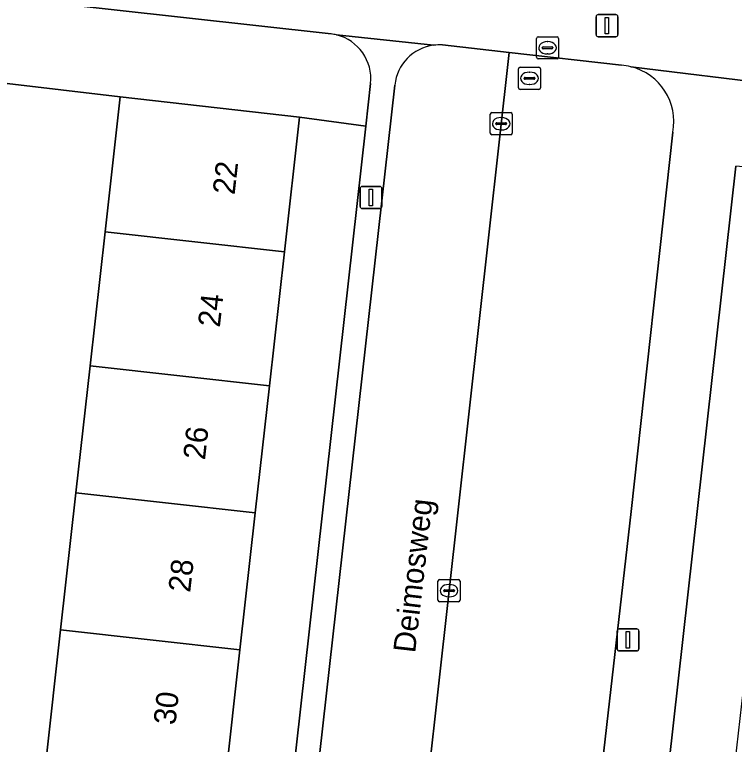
# Model space of a CAD drawing. Extents: x 161928 to 163071, y 386474 to 387428.
# Drawn here: x 162199.57 to 162232.12, y 386884.42 to 386917.4 of the extents above; entities that cross this region are included whole.
import ezdxf

# ---------------------------------------------------------------- set-up
doc = ezdxf.new("R2010")
doc.units = 0
for name, color, linetype in [('IMGEO_Brandkraan', 7, 'Continuous'), ('IMGEO_Erf', 7, 'Continuous'), ('IMGEO_Groenvoorziening', 7, 'Continuous'), ('IMGEO_Kolk', 7, 'Continuous'), ('IMGEO_Lichtmast', 7, 'Continuous'), ('IMGEO_Openbare_ruimte_label', 7, 'Continuous'), ('IMGEO_Pand', 7, 'Continuous'), ('IMGEO_Pand_nummerreeks', 7, 'Continuous'), ('IMGEO_Parkeervlak_open', 7, 'Continuous'), ('IMGEO_Rijbaan_lokaal_open', 7, 'Continuous'), ('IMGEO_Rioolput', 7, 'Continuous'), ('IMGEO_Voetpad_open', 7, 'Continuous')]:
    doc.layers.add(name, color=color, linetype=linetype)

msp = doc.modelspace()

# ---------------------------------------------------------------- linework, layer by layer
at = {"layer": 'IMGEO_Brandkraan'}
for p, q in [((162223.173, 386915.472), (162223.173, 386916.324)), ((162223.248, 386916.398), (162224.1, 386916.398)), ((162223.661, 386916.178), (162223.686, 386916.178)), ((162224.174, 386916.324), (162224.174, 386915.472)), ((162223.432, 386915.892), (162223.432, 386915.904)), ((162223.87, 386915.855), (162223.472, 386915.855)), ((162223.475, 386915.941), (162223.873, 386915.941)), ((162223.916, 386915.904), (162223.916, 386915.892)), ((162223.684, 386915.618), (162223.659, 386915.618)), ((162224.1, 386915.398), (162223.248, 386915.398))]:
    msp.add_line(p, q, dxfattribs=at)
for points in [[(162223.173, 386915.472), (162223.173, 386916.324)], [(162223.248, 386916.398), (162224.1, 386916.398)], [(162224.174, 386916.324), (162224.174, 386915.472)], [(162224.1, 386915.398), (162223.248, 386915.398)]]:
    msp.add_lwpolyline(points, dxfattribs=at)
for centre, radius, start, end in [((162223.25, 386916.322), 0.0765, 91.552, 178.448), ((162223.25, 386916.322), 0.0765, 91.552, 178.448), ((162224.098, 386916.322), 0.0765, 1.552, 88.448), ((162224.098, 386916.322), 0.0765, 1.552, 88.448), ((162223.472, 386915.901), 0.0403, 85.8775, 175.7526), ((162223.469, 386915.891), 0.0366, 178.938, 274.7102), ((162223.873, 386915.898), 0.043, 264.8664, 352.4533), ((162223.877, 386915.903), 0.0386, 1.7309, 96.639), ((162223.25, 386915.474), 0.0765, 181.552, 268.448), ((162223.25, 386915.474), 0.0765, 181.552, 268.448), ((162224.098, 386915.474), 0.0765, 271.552, 358.448), ((162224.098, 386915.474), 0.0765, 271.552, 358.448)]:
    msp.add_arc(centre, radius, start, end, dxfattribs=at)
for centre, major_axis, ratio, start_param, end_param in [((162223.66, 386915.898), (-0.387, 0.002), 0.722429, 4.712389, 7.853982), ((162223.685, 386915.898), (-0.39, 0.002), 0.717154, 1.570796, 4.712389)]:
    msp.add_ellipse(centre, major_axis=major_axis, ratio=ratio, start_param=start_param, end_param=end_param, dxfattribs=at)
at = {"layer": 'IMGEO_Erf'}
for points in [[(162200.985, 386883.612), (162201.654, 386889.599), (162202.345, 386895.789), (162202.986, 386901.531), (162203.663, 386907.586), (162204.343, 386913.676), (162196.021, 386914.657)], [(162208.562, 386850.925), (162215.453, 386912.353), (162212.452, 386912.769), (162211.772, 386906.681), (162211.096, 386900.626), (162210.454, 386894.884), (162209.763, 386888.694), (162209.094, 386882.707), (162208.433, 386876.788), (162207.776, 386870.913), (162207.09, 386864.77), (162206.45, 386859.042), (162205.758, 386852.844), (162197.649, 386853.75), (162194.899, 386854.057), (162195.575, 386860.111), (162198.325, 386859.804), (162198.341, 386859.947), (162198.981, 386865.675), (162199.667, 386871.818), (162200.324, 386877.693), (162200.985, 386883.612)], [(162231.776, 386880.288), (162232.455, 386886.249), (162233.134, 386892.21), (162233.812, 386898.172), (162234.491, 386904.133), (162235.191, 386910.281), (162232.179, 386910.543), (162225.231, 386848.529)]]:
    msp.add_lwpolyline(points, dxfattribs=at)
at = {"layer": 'IMGEO_Groenvoorziening'}
msp.add_lwpolyline([(162213.884, 386916.523), (162194.106, 386918.722), (162193.675, 386914.924), (162196.021, 386914.657), (162204.343, 386913.676), (162212.452, 386912.769), (162215.453, 386912.353), (162215.669, 386914.282)], dxfattribs=at)
for centre, radius, start, end in [((162213.637, 386914.382), 2.155, 76.7639, 83.4062), ((162213.653, 386914.508), 2.028, 353.5924, 76.4056)]:
    msp.add_arc(centre, radius, start, end, dxfattribs=at)
at = {"layer": 'IMGEO_Kolk'}
for p, q in [((162221.078, 386912.042), (162221.078, 386912.894)), ((162221.153, 386912.968), (162222.005, 386912.968)), ((162222.079, 386912.894), (162222.079, 386912.042)), ((162221.38, 386912.511), (162221.778, 386912.511)), ((162221.566, 386912.748), (162221.591, 386912.748)), ((162221.337, 386912.462), (162221.337, 386912.474)), ((162221.775, 386912.425), (162221.377, 386912.425)), ((162221.589, 386912.188), (162221.564, 386912.188)), ((162221.821, 386912.474), (162221.821, 386912.462)), ((162222.005, 386911.968), (162221.153, 386911.968)), ((162218.718, 386890.939), (162218.718, 386891.791)), ((162218.793, 386891.865), (162219.645, 386891.865)), ((162219.719, 386891.791), (162219.719, 386890.939)), ((162218.977, 386891.359), (162218.977, 386891.371)), ((162219.02, 386891.408), (162219.418, 386891.408)), ((162219.206, 386891.645), (162219.231, 386891.645)), ((162219.461, 386891.371), (162219.461, 386891.359)), ((162219.415, 386891.322), (162219.017, 386891.322)), ((162219.229, 386891.085), (162219.204, 386891.085)), ((162219.645, 386890.865), (162218.793, 386890.865))]:
    msp.add_line(p, q, dxfattribs=at)
for points in [[(162221.078, 386912.042), (162221.078, 386912.894)], [(162221.153, 386912.968), (162222.005, 386912.968)], [(162222.079, 386912.894), (162222.079, 386912.042)], [(162222.005, 386911.968), (162221.153, 386911.968)], [(162218.718, 386890.939), (162218.718, 386891.791)], [(162218.793, 386891.865), (162219.645, 386891.865)], [(162219.719, 386891.791), (162219.719, 386890.939)], [(162219.645, 386890.865), (162218.793, 386890.865)]]:
    msp.add_lwpolyline(points, dxfattribs=at)
for centre, radius, start, end in [((162221.155, 386912.892), 0.0765, 91.552, 178.448), ((162221.155, 386912.892), 0.0765, 91.552, 178.448), ((162222.003, 386912.892), 0.0765, 1.552, 88.448), ((162222.003, 386912.892), 0.0765, 1.552, 88.448), ((162221.377, 386912.471), 0.0403, 85.8775, 175.7526), ((162221.782, 386912.473), 0.0386, 1.7309, 96.639), ((162221.374, 386912.461), 0.0366, 178.938, 274.7102), ((162221.778, 386912.468), 0.043, 264.8664, 352.4533), ((162221.155, 386912.044), 0.0765, 181.552, 268.448), ((162221.155, 386912.044), 0.0765, 181.552, 268.448), ((162222.003, 386912.044), 0.0765, 271.552, 358.448), ((162222.003, 386912.044), 0.0765, 271.552, 358.448), ((162218.795, 386891.789), 0.0765, 91.552, 178.448), ((162218.795, 386891.789), 0.0765, 91.552, 178.448), ((162219.643, 386891.789), 0.0765, 1.552, 88.448), ((162219.643, 386891.789), 0.0765, 1.552, 88.448), ((162219.017, 386891.368), 0.0403, 85.8775, 175.7526), ((162219.422, 386891.37), 0.0386, 1.7309, 96.639), ((162219.014, 386891.358), 0.0366, 178.938, 274.7102), ((162219.418, 386891.365), 0.043, 264.8664, 352.4533), ((162218.795, 386890.941), 0.0765, 181.552, 268.448), ((162218.795, 386890.941), 0.0765, 181.552, 268.448), ((162219.643, 386890.941), 0.0765, 271.552, 358.448), ((162219.643, 386890.941), 0.0765, 271.552, 358.448)]:
    msp.add_arc(centre, radius, start, end, dxfattribs=at)
for centre, major_axis, ratio, start_param, end_param in [((162221.565, 386912.468), (-0.387, 0.002), 0.722429, 4.712389, 7.853982), ((162221.59, 386912.468), (-0.39, 0.002), 0.717154, 1.570796, 4.712389), ((162219.205, 386891.365), (-0.387, 0.002), 0.722429, 4.712389, 7.853982), ((162219.23, 386891.365), (-0.39, 0.002), 0.717154, 1.570796, 4.712389)]:
    msp.add_ellipse(centre, major_axis=major_axis, ratio=ratio, start_param=start_param, end_param=end_param, dxfattribs=at)
at = {"layer": 'IMGEO_Lichtmast'}
for p, q in [((162225.865, 386916.499), (162225.865, 386917.299)), ((162225.865, 386917.299), (162225.865, 386916.499)), ((162225.965, 386917.399), (162226.755, 386917.399)), ((162226.755, 386917.399), (162225.965, 386917.399)), ((162226.855, 386917.299), (162226.855, 386916.499)), ((162226.855, 386916.499), (162226.855, 386917.299)), ((162226.755, 386916.399), (162225.965, 386916.399)), ((162225.965, 386916.399), (162226.755, 386916.399)), ((162215.193, 386908.733), (162215.193, 386909.533)), ((162215.193, 386909.533), (162215.193, 386908.733)), ((162215.293, 386909.633), (162216.083, 386909.633)), ((162216.083, 386909.633), (162215.293, 386909.633)), ((162216.183, 386909.533), (162216.183, 386908.733)), ((162216.183, 386908.733), (162216.183, 386909.533)), ((162216.083, 386908.633), (162215.293, 386908.633)), ((162215.293, 386908.633), (162216.083, 386908.633)), ((162226.814, 386888.739), (162226.814, 386889.539)), ((162226.814, 386889.539), (162226.814, 386888.739)), ((162226.914, 386889.639), (162227.704, 386889.639)), ((162227.704, 386889.639), (162226.914, 386889.639)), ((162227.804, 386889.539), (162227.804, 386888.739)), ((162227.804, 386888.739), (162227.804, 386889.539)), ((162227.704, 386888.639), (162226.914, 386888.639)), ((162226.914, 386888.639), (162227.704, 386888.639))]:
    msp.add_line(p, q, dxfattribs=at)
for points in [[(162226.285, 386917.274), (162226.435, 386917.274), (162226.435, 386916.524), (162226.285, 386916.524), (162226.285, 386917.274)], [(162215.613, 386909.508), (162215.763, 386909.508), (162215.763, 386908.758), (162215.613, 386908.758), (162215.613, 386909.508)], [(162227.234, 386889.514), (162227.384, 386889.514), (162227.384, 386888.764), (162227.234, 386888.764), (162227.234, 386889.514)]]:
    msp.add_lwpolyline(points, dxfattribs=at)
for centre, start, end in [((162225.965, 386917.299), 90, 180), ((162225.965, 386917.299), 90, 180), ((162226.755, 386917.299), 0, 90), ((162226.755, 386917.299), 360, 90), ((162225.965, 386916.499), 180, 270), ((162225.965, 386916.499), 180, 270), ((162226.755, 386916.499), 270, 0), ((162226.755, 386916.499), 270, 0), ((162215.293, 386909.533), 90, 180), ((162215.293, 386909.533), 90, 180), ((162216.083, 386909.533), 0, 90), ((162216.083, 386909.533), 360, 90), ((162215.293, 386908.733), 180, 270), ((162215.293, 386908.733), 180, 270), ((162216.083, 386908.733), 270, 0), ((162216.083, 386908.733), 270, 0), ((162226.914, 386889.539), 90, 180), ((162226.914, 386889.539), 90, 180), ((162227.704, 386889.539), 0, 90), ((162227.704, 386889.539), 360, 90), ((162226.914, 386888.739), 180, 270), ((162226.914, 386888.739), 180, 270), ((162227.704, 386888.739), 270, 0), ((162227.704, 386888.739), 270, 0)]:
    msp.add_arc(centre, 0.1, start, end, dxfattribs=at)
at = {"layer": 'IMGEO_Pand'}
for points in [[(162211.772, 386906.681), (162212.452, 386912.769), (162204.343, 386913.676), (162203.663, 386907.586)], [(162203.663, 386907.586), (162202.986, 386901.531), (162211.096, 386900.626), (162211.772, 386906.681)], [(162210.454, 386894.884), (162211.096, 386900.626), (162202.986, 386901.531), (162202.345, 386895.789)], [(162209.763, 386888.694), (162210.454, 386894.884), (162202.345, 386895.789), (162201.654, 386889.599)], [(162201.654, 386889.599), (162200.985, 386883.612), (162209.094, 386882.707), (162209.763, 386888.694)]]:
    msp.add_lwpolyline(points, close=True, dxfattribs=at)
at = {"layer": 'IMGEO_Parkeervlak_open'}
for points in [[(162227.02, 386915.113), (162221.937, 386915.685), (162217.824, 386878.802)], [(162225.975, 386882.023), (162227.454, 386894.935), (162229.34, 386912.083)]]:
    msp.add_lwpolyline(points, dxfattribs=at)
for centre, radius, start, end in [((162226.834, 386912.624), 2.496, 75.9244, 85.7252), ((162226.827, 386912.562), 2.558, 349.2173, 76.1123)]:
    msp.add_arc(centre, radius, start, end, dxfattribs=at)
at = {"layer": 'IMGEO_Rijbaan_lokaal_open'}
for points in [[(162221.937, 386915.685), (162218.916, 386916.025)], [(162216.766, 386914.216), (162209.374, 386848.391), (162211.872, 386848.108), (162214.37, 386847.825), (162217.824, 386878.802), (162221.937, 386915.685)]]:
    msp.add_lwpolyline(points, dxfattribs=at)
for centre, radius, start, end in [((162218.783, 386914.001), 2.028, 97.5077, 173.9133), ((162218.785, 386913.937), 2.092, 86.4103, 97.3313)]:
    msp.add_arc(centre, radius, start, end, dxfattribs=at)
at = {"layer": 'IMGEO_Rioolput'}
for p, q in [((162222.357, 386914.092), (162222.357, 386914.944)), ((162222.432, 386915.018), (162223.284, 386915.018)), ((162222.845, 386914.798), (162222.87, 386914.798)), ((162223.358, 386914.944), (162223.358, 386914.092)), ((162222.616, 386914.512), (162222.616, 386914.524)), ((162223.054, 386914.475), (162222.656, 386914.475)), ((162222.659, 386914.561), (162223.057, 386914.561)), ((162223.1, 386914.524), (162223.1, 386914.512)), ((162222.868, 386914.238), (162222.843, 386914.238)), ((162223.284, 386914.018), (162222.432, 386914.018))]:
    msp.add_line(p, q, dxfattribs=at)
for points in [[(162222.357, 386914.092), (162222.357, 386914.944)], [(162222.432, 386915.018), (162223.284, 386915.018)], [(162223.358, 386914.944), (162223.358, 386914.092)], [(162223.284, 386914.018), (162222.432, 386914.018)]]:
    msp.add_lwpolyline(points, dxfattribs=at)
for centre, radius, start, end in [((162222.434, 386914.942), 0.0765, 91.552, 178.448), ((162222.434, 386914.942), 0.0765, 91.552, 178.448), ((162223.282, 386914.942), 0.0765, 1.552, 88.448), ((162223.282, 386914.942), 0.0765, 1.552, 88.448), ((162222.656, 386914.521), 0.0403, 85.8775, 175.7526), ((162222.653, 386914.511), 0.0366, 178.938, 274.7102), ((162223.057, 386914.518), 0.043, 264.8664, 352.4533), ((162223.061, 386914.523), 0.0386, 1.7309, 96.639), ((162222.434, 386914.094), 0.0765, 181.552, 268.448), ((162222.434, 386914.094), 0.0765, 181.552, 268.448), ((162223.282, 386914.094), 0.0765, 271.552, 358.448), ((162223.282, 386914.094), 0.0765, 271.552, 358.448)]:
    msp.add_arc(centre, radius, start, end, dxfattribs=at)
for centre, major_axis, ratio, start_param, end_param in [((162222.844, 386914.518), (-0.387, 0.002), 0.722429, 4.712389, 7.853982), ((162222.869, 386914.518), (-0.39, 0.002), 0.717154, 1.570796, 4.712389)]:
    msp.add_ellipse(centre, major_axis=major_axis, ratio=ratio, start_param=start_param, end_param=end_param, dxfattribs=at)
at = {"layer": 'IMGEO_Voetpad_open'}
for points in [[(162169.498, 386924.436), (162165.657, 386924.87), (162165.32, 386921.935), (162170.154, 386921.384), (162173.232, 386921.042), (162192.218, 386918.931), (162194.106, 386918.722), (162213.884, 386916.523)], [(162214.13, 386916.48), (162218.518, 386916.012)], [(162218.518, 386916.012), (162214.13, 386916.48)], [(162218.916, 386916.025), (162221.937, 386915.685), (162227.02, 386915.113)], [(162227.441, 386915.045), (162234.123, 386914.229)], [(162234.123, 386914.229), (162227.441, 386915.045)], [(162206.167, 386848.791), (162209.374, 386848.391), (162216.766, 386914.216)], [(162215.669, 386914.282), (162215.453, 386912.353), (162208.562, 386850.925)], [(162229.34, 386912.083), (162227.454, 386894.935), (162225.975, 386882.023)], [(162225.231, 386848.529), (162232.179, 386910.543)]]:
    msp.add_lwpolyline(points, dxfattribs=at)
for centre, radius, start, end in [((162213.637, 386914.382), 2.155, 76.7639, 83.4062), ((162213.653, 386914.508), 2.028, 353.5924, 76.4056), ((162218.783, 386914.001), 2.028, 97.5077, 173.9133), ((162218.785, 386913.937), 2.092, 86.4103, 97.3313), ((162226.834, 386912.624), 2.496, 75.9244, 85.7252), ((162226.827, 386912.562), 2.558, 349.2173, 76.1123)]:
    msp.add_arc(centre, radius, start, end, dxfattribs=at)

# ---------------------------------------------------------------- texts
at = {"layer": 'IMGEO_Openbare_ruimte_label'}
msp.add_text('Deimosweg', height=1, rotation=83.4574, dxfattribs=at).set_placement((162217.684, 386888.521))
at = {"layer": 'IMGEO_Pand_nummerreeks'}
for s, p in [('22', (162209.52, 386909.229)), ('24', (162208.852, 386903.239)), ('26', (162208.182, 386897.247)), ('28', (162207.513, 386891.257)), ('30', (162206.844, 386885.265))]:
    msp.add_text(s, height=1, rotation=83.6261, dxfattribs=at).set_placement(p)

doc.saveas('drawing.dxf')
